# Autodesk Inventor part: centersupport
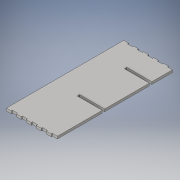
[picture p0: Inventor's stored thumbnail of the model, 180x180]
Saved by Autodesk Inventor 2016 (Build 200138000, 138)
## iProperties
Created: 2017-03
Part Number: centersupport
Material: Generic
Document SubType Name: Modeling
Designer: Corey
Density: 1 g/cm^3
Appearance: Default
Author: Corey
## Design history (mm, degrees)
sketch "Sketch1"
  geometry: L1 (0, 0)-(368.3, 0); L2 (368.3, 0)-(368.3, -866.902); L3 (368.3, -866.902)-(0, -866.902); L4 (0, -866.902)-(0, 0)
  constraints: 8 end point, 2 parallel, 1 horizontal, 1 perpendicular
  dimensions: "d0" = 368.3 distance of L2.end L3.end (= panel); "d1" = 866.902 distance between parallel lines of L3 L1 (= shoe + 2 x sweater + 3 x thick)
extrude "body" new body sketch "Sketch1" distance "d2" = 18.034 (= thick); taper "d3" = 0 deg
sketch "Sketch2"
  geometry: L1 (0, 0)-(0, 866.902) reference; L2 (0, 0)-(-36.83, 0); L3 (-36.83, 0)-(-36.83, 9.017); L4 (-36.83, 9.017)-(0, 9.017); L5 (0, 9.017)-(0, 0); L6 (0, 433.451)-(-368.3, 433.451); L7 (-368.3, 866.902)-(-368.3, 0) reference; L8 (0, 866.902)-(-36.83, 866.902); L9 (-36.83, 866.902)-(-36.83, 857.885); L10 (-36.83, 857.885)-(0, 857.885); L11 (0, 857.885)-(0, 866.902)
  constraints: 18 end point, 3 symmetric about line, 2 midpoint, 2 parallel, 1 horizontal, 1 perpendicular
  dimensions: "d4" = 36.83 distance of L3.end L4.end (= 0.1 x panel); "d5" = 9.017 distance of L2.end L3.end (= 0.5 x thick)
extrude "Extrusion2" cut sketch "Sketch2" stored distance "d6" = 18.034 (= thick); taper "d7" = 0 deg
pattern_linear "Rectangular Pattern1" dims "d10" = 73.66 (= 0.2 x panel)
sketch "Sketch3"
  geometry: L1 (0, 9.017)-(0, 857.885) reference; L2 (0, 339.217)-(-184.15, 339.217); L3 (-184.15, 339.217)-(-184.15, 357.251); L4 (-184.15, 357.251)-(0, 357.251); L5 (0, 357.251)-(0, 339.217); L6 (-110.49, 9.017)-(-73.66, 9.017) reference; L7 (0, 687.451)-(-184.15, 687.451); L8 (-184.15, 687.451)-(-184.15, 705.485); L9 (-184.15, 705.485)-(0, 705.485); L10 (0, 705.485)-(0, 687.451); 1 further point
  constraints: 16 end point, 4 parallel, 2 horizontal, 2 perpendicular, 1 collinear, 1 point on line
  dimensions: "d11" = 184.15 distance of L3.end L4.end (= 0.5 x panel); "d12" = 18.034 distance of L2.end L3.end (= thick); "d13" = 330.2 distance between parallel lines of L6 L2 (= sweater); "d14" = 184.15 distance of L8.end L9.end (= 0.5 x d17); "d15" = 18.034 distance of L7.end L8.end (= thick); "d18" = 330.2 distance between parallel lines of L7 L4 (= sweater)
extrude "Extrusion3" cut sketch "Sketch3" stored distance "d19" = 18.034 (= thick); taper "d20" = 0 deg
body "Solid1"
other parameters: "thick" = 18.034 [user parameter; used in 7 equation terms], "top" = 152.4 [user parameter], "bit" = 6.35 [user parameter], "depth" = 425.45 [user parameter], "height" = 1917.7 [user parameter], "width" = 1117.6 [user parameter], "panel" = 368.3 [user parameter; used in 4 equation terms], "shoe" = 152.4 [user parameter; used in 1 equation term], "sweater" = 330.2 [user parameter; used in 3 equation terms], "d16" = 19.05 [user parameter], "d17" = 368.3 [user parameter; used in 1 equation term], "osb" = 19.05 [user parameter]
